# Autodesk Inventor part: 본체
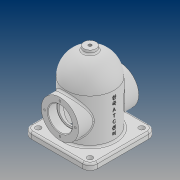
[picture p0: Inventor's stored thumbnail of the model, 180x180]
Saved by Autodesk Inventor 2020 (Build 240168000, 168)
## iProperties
Created: 2021-08
Part Number: 본체
Material: 일반
Document SubType Name: Modeling
Designer: PC312-
Density: 1 g/cm^3
Appearance: 기본값
Mass: 320.706 g
Surface Area: 800.755 cm^2
Volume: 320.706 cm^3
Author: PC312-
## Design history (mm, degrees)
sketch "스케치4"
  geometry: L1 (0, 0)-(124, 0); L2 (84, -40)-(0, -40); L3 (0, -40)-(0, 0); A1 r 40 centre (84, 0) between (84, -40) and (124, 0)
  constraints: 6 end point, 2 horizontal, 2 point on circle, 1 centre point, 1 horizontal alignment, 1 tangent, 1 vertical, 1 vertical alignment
  dimensions: "d5" = 124 distance of L1.end L1.start; "d6" = 80 diameter of A1
revolve "회전1" sketch "스케치4" stored, may be unused: angle "d7" = 90 deg
feature "쉘1" dims "d8" = 8
sketch "스케치5"
  geometry: L1 (-55, 55)-(55, 55); L2 (55, 55)-(55, -55); L3 (55, -55)-(-55, -55); L4 (-55, -55)-(-55, 55); L5 (-55, 55)-(55, -55); L6 (55, 55)-(-55, -55); C1 r 32 at (0, 0) reference; 1 further point
  constraints: 12 end point, 2 midpoint, 2 parallel, 1 horizontal, 1 perpendicular
  dimensions: "d9" = 110 distance of L1.end L2.end; "d10" = 110 distance of L2.end L3.end
extrude "돌출2" join sketch "스케치5" distance "d11" = 10; taper "d12" = 0 deg
node "작업 평면1"
sketch "스케치6"
  geometry: L1 (55, 0)-(-55, 0) reference; C1 r 31 at (0, 48); 2 further points
  constraints: 1 centre point, 1 midpoint, 1 vertical alignment
  dimensions: "d14" = 62 diameter of C1; "d15" = 48 distance from line of L1 C1.centre
extrude "돌출3" join sketch "스케치6" stored distance "d16" = 10; taper "d17" = 0 deg
sketch "스케치7"
  geometry: L1 (55, -48)-(-55, -48) reference; C1 r 20 at (0, 0); C2 r 31 at (0, 0) reference; 2 further points
  constraints: 1 centre point, 1 concentric, 1 midpoint, 1 vertical alignment
  dimensions: "d18" = 40 diameter of C1
extrude "돌출4" cut sketch "스케치7" distance "d19" = 15; taper "d20" = 0 deg
sketch "스케치9"
  geometry: C1 r 16.5 at (0, 0); C2 r 20 at (0, 0) reference; 1 further point
  constraints: 1 centre point, 1 concentric
  dimensions: "d21" = 33 diameter of C1
extrude "돌출5" cut sketch "스케치9" extent not by distance; stored distance "d22" = 15; taper "d23" = 0 deg
sketch "스케치10"
  geometry: C1 r 31 at (0, 0) reference; 2 further points
  constraints: 1 vertical alignment
  dimensions: "d24" = 25.5 distance of point (0, -25.5) C1.centre
hole "구멍1" sketch "스케치10" at (0, -25.5) diameter "d25" = 3.242; stored, may be unused: countersink angle "d29" = 90 deg, drill point angle "d31" = 118 deg; dims "d26" = 8, "d27" = 4, "d28" = 2, "d30" = 10
sketch "스케치11"
  geometry: L1 (-55, 55)-(-55, -55) reference; L2 (-55, -55)-(55, -55) reference; C1 r 4.5 at (-43, -43); 1 further point
  constraints: 1 centre point
  dimensions: "d35" = 9 diameter of C1; "d36" = 12 distance from line of L1 C1.centre; "d37" = 12 distance from line of L2 C1.centre
extrude "돌출6" cut sketch "스케치11" extent not by distance; stored distance "d38" = 0; taper "d39" = 0 deg
node "작업 평면2"
sketch "스케치12"
  geometry: C1 r 10 at (55, -55); 1 further point
  constraints: 1 centre point, 1 coincident
  dimensions: "d47" = 20 diameter of C1
extrude "돌출7" join sketch "스케치12" stored distance "d48" = 15; taper "d49" = 0 deg
sketch "스케치13"
  geometry: C1 r 10 at (0, 0) reference; 2 further points
  constraints: 1 coincident
hole "구멍2" sketch "스케치13" at (0, 0) diameter "d50" = 5.1881; stored, may be unused: countersink angle "d54" = 90 deg, drill point angle "d56" = 0 deg; dims "d51" = 12, "d52" = 4, "d53" = 2, "d55" = 30
fillet "모깎기1" dims "d57" = 12
chamfer "모따기1" distance "d58" = 1; stored, may be unused: second distance "d59" = 2, angle "d60" = 45 deg
fillet "모깎기2" dims "d61" = 3
fillet "모깎기3" dims "d62" = 3
fillet "모깎기4" dims "d63" = 3
fillet "모깎기5" dims "d64" = 3
node "작업 평면3"
sketch "스케치14" dims "d6" = 80
  geometry: L1 (0, -43)-(0, 43) reference; 3 further points
  constraints: 1 horizontal alignment, 1 midpoint, 1 other
  dimensions: "d66" = 48 distance from line of L1 point (48, 0)
feature "엠보싱1" sketch "스케치14" dims "d67" = 0.5, "d68" = 0
fillet "모깎기6" dims "d69" = 0.3
node "솔리드2"
mirror "미러1"
pattern_circular "원형 패턴1" dims angle "d33" = 360 deg
mirror "미러2"
pattern_linear "직사각형 패턴1" dims "d42" = 86, "d45" = 86
feature "A9D066F2-1C7D-4E18-AEED-F7BC21143FA4" dims "d25" = 3.242, "d26" = 8, "d27" = 4, "d28" = 2, "d29" = 90 deg, "d30" = 10, "d31" = 118 deg
other parameters: "d46" = -129, "d65" = 46.5
